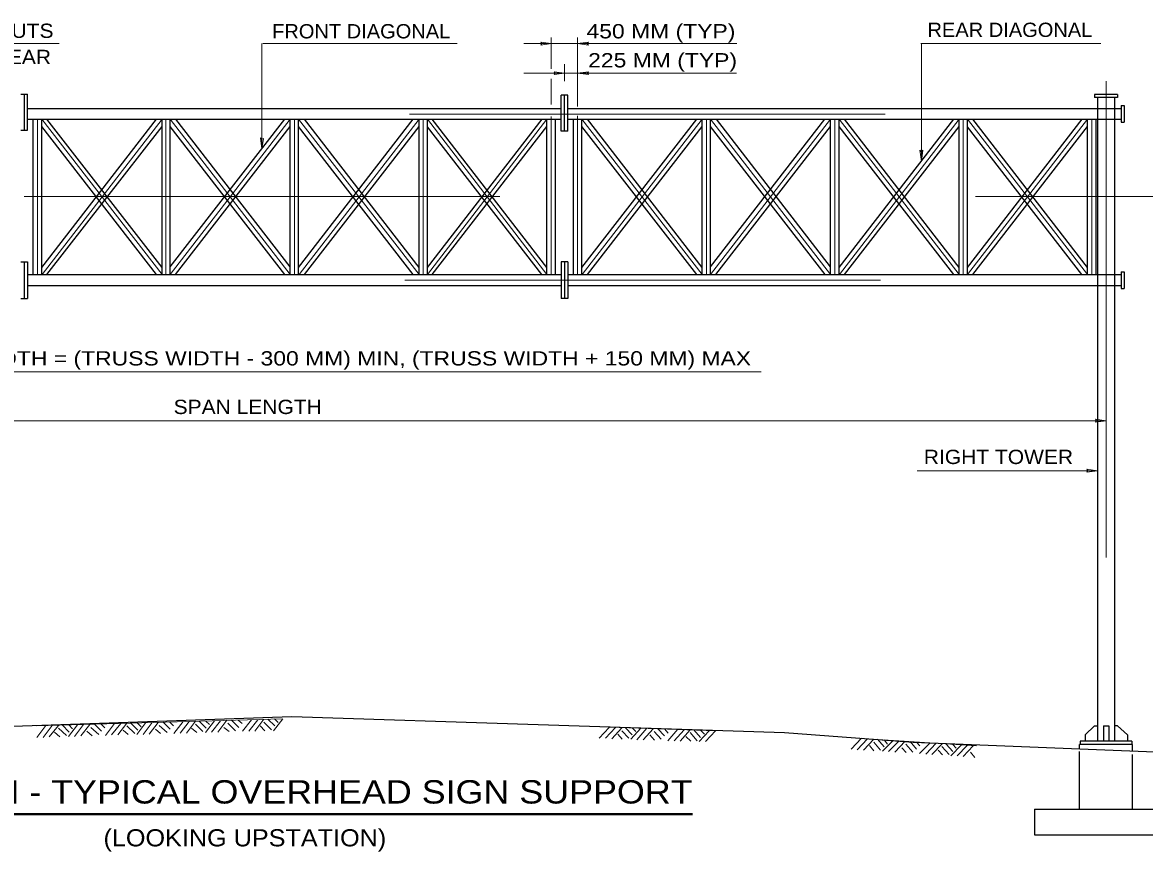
# Model space of a CAD drawing. Extents: x 312601.858 to 312602.699, y 144420.109 to 144420.704.
# Drawn here: x 312602.1757 to 312602.4116, y 144420.4027 to 144420.5768 of the extents above; entities that cross this region are included whole.
import ezdxf
from ezdxf.enums import TextEntityAlignment as Align

# ---------------------------------------------------------------- set-up
doc = ezdxf.new("R2010")
doc.units = 0
doc.header["$LTSCALE"] = 0.0012
doc.linetypes.add('DOT_DASHED', pattern=[7.7, 5, -1.2, 0.3, -1.2])
doc.linetypes.add('LONG_DASHED', pattern=[7.5, 6, -1.5])
doc.layers.add('1', color=7, linetype='Continuous', lineweight=25)
doc.layers.add('2', color=7, linetype='Continuous', lineweight=13)

msp = doc.modelspace()

# ---------------------------------------------------------------- linework, layer by layer
at = {"layer": '1', "lineweight": 13}
for p, q in [((312602.2869, 144420.5737), (312602.2869, 144420.5671)), ((312602.2924, 144420.5737), (312602.2924, 144420.5592)), ((312602.1392, 144420.5724), (312602.1835, 144420.5724)), ((312602.2263, 144420.5724), (312602.2671, 144420.5724)), ((312602.3646, 144420.5724), (312602.4024, 144420.5724)), ((312602.3647, 144420.5724), (312602.3647, 144420.5477)), ((312602.2897, 144420.5645), (312602.2897, 144420.5681)), ((312602.2869, 144420.565), (312602.2869, 144420.5596)), ((312602.4053, 144420.5127), (312602.4053, 144420.5139)), ((312602.0623, 144420.4932), (312602.4035, 144420.4932)), ((312602.3638, 144420.4827), (312602.4017, 144420.4827)), ((312602.4053, 144420.431), (312602.4053, 144420.4322))]:
    msp.add_line(p, q, dxfattribs=at)
at = {"layer": '1', "linetype": 'DOT_DASHED', "lineweight": 13}
for p, q in [((312602.4035, 144420.5645), (312602.4035, 144420.4281)), ((312602.0571, 144420.5576), (312602.4098, 144420.5576)), ((312602.1789, 144420.5239), (312602.1789, 144420.5565)), ((312602.2051, 144420.5239), (312602.1798, 144420.5565)), ((312602.1799, 144420.5239), (312602.2051, 144420.5565)), ((312602.2059, 144420.5239), (312602.2059, 144420.5565)), ((312602.232, 144420.5239), (312602.2068, 144420.5565)), ((312602.2068, 144420.5239), (312602.232, 144420.5565)), ((312602.2329, 144420.5239), (312602.2329, 144420.5565)), ((312602.2591, 144420.5239), (312602.2338, 144420.5565)), ((312602.2339, 144420.5239), (312602.2591, 144420.5565)), ((312602.26, 144420.5239), (312602.26, 144420.5565)), ((312602.2609, 144420.5565), (312602.286, 144420.5239)), ((312602.2609, 144420.5239), (312602.286, 144420.5565)), ((312602.2869, 144420.5571), (312602.2869, 144420.5239)), ((312602.2924, 144420.5572), (312602.2924, 144420.5239)), ((312602.3186, 144420.5239), (312602.2933, 144420.5565)), ((312602.2934, 144420.5239), (312602.3186, 144420.5565)), ((312602.3195, 144420.5239), (312602.3195, 144420.5565)), ((312602.3456, 144420.5239), (312602.3204, 144420.5565)), ((312602.3204, 144420.5239), (312602.3456, 144420.5565)), ((312602.3465, 144420.5239), (312602.3465, 144420.5565)), ((312602.3726, 144420.5239), (312602.3474, 144420.5565)), ((312602.3475, 144420.5239), (312602.3726, 144420.5565)), ((312602.3735, 144420.5239), (312602.3735, 144420.5565)), ((312602.3744, 144420.5565), (312602.3996, 144420.5239)), ((312602.3744, 144420.5239), (312602.3996, 144420.5565)), ((312602.4005, 144420.5565), (312602.4005, 144420.5239)), ((312602.1761, 144420.5403), (312602.4195, 144420.5403)), ((312602.0561, 144420.5227), (312602.4099, 144420.5227))]:
    msp.add_line(p, q, dxfattribs=at)
at = {"layer": '1'}
for p, q in [((312602.1754, 144420.5618), (312602.1768, 144420.5618)), ((312602.1761, 144420.5618), (312602.1761, 144420.5542)), ((312602.2904, 144420.5616), (312602.289, 144420.5616)), ((312602.2897, 144420.554), (312602.2897, 144420.5616)), ((312602.2904, 144420.554), (312602.2904, 144420.5616)), ((312602.4059, 144420.5617), (312602.4011, 144420.5617)), ((312602.4011, 144420.5617), (312602.4011, 144420.5611)), ((312602.4059, 144420.5617), (312602.4059, 144420.5611)), ((312602.4059, 144420.5611), (312602.4011, 144420.5611)), ((312602.4017, 144420.5611), (312602.4017, 144420.4259)), ((312602.4053, 144420.5611), (312602.4053, 144420.4259)), ((312602.4067, 144420.5594), (312602.4067, 144420.5559)), ((312602.4067, 144420.5594), (312602.4073, 144420.5594)), ((312602.4073, 144420.5594), (312602.4073, 144420.5559)), ((312602.1768, 144420.5565), (312602.289, 144420.5565)), ((312602.178, 144420.5239), (312602.178, 144420.5565)), ((312602.1798, 144420.5239), (312602.1798, 144420.5565)), ((312602.2051, 144420.5254), (312602.1809, 144420.5565)), ((312602.2051, 144420.5239), (312602.2051, 144420.5565)), ((312602.2068, 144420.5239), (312602.2068, 144420.5565)), ((312602.2068, 144420.5255), (312602.2309, 144420.5565)), ((312602.232, 144420.5239), (312602.232, 144420.5565)), ((312602.2338, 144420.5239), (312602.2338, 144420.5565)), ((312602.2591, 144420.5254), (312602.235, 144420.5565)), ((312602.2591, 144420.5239), (312602.2591, 144420.5565)), ((312602.2609, 144420.5239), (312602.2609, 144420.5565)), ((312602.2609, 144420.5254), (312602.285, 144420.5565)), ((312602.286, 144420.5239), (312602.286, 144420.5565)), ((312602.2878, 144420.5239), (312602.2878, 144420.5565)), ((312602.2904, 144420.5588), (312602.4017, 144420.5588)), ((312602.2904, 144420.5565), (312602.4017, 144420.5565)), ((312602.2916, 144420.5239), (312602.2916, 144420.5565)), ((312602.2933, 144420.5239), (312602.2933, 144420.5565)), ((312602.3186, 144420.5254), (312602.2945, 144420.5565)), ((312602.3186, 144420.5239), (312602.3186, 144420.5565)), ((312602.3204, 144420.5239), (312602.3204, 144420.5565)), ((312602.3204, 144420.5255), (312602.3444, 144420.5565)), ((312602.3456, 144420.5239), (312602.3456, 144420.5565)), ((312602.3474, 144420.5239), (312602.3474, 144420.5565)), ((312602.3726, 144420.5254), (312602.3485, 144420.5565)), ((312602.3726, 144420.5239), (312602.3726, 144420.5565)), ((312602.3744, 144420.5239), (312602.3744, 144420.5565)), ((312602.3744, 144420.5254), (312602.3985, 144420.5565)), ((312602.3996, 144420.5239), (312602.3996, 144420.5565)), ((312602.4014, 144420.5239), (312602.4014, 144420.5565)), ((312602.4053, 144420.5588), (312602.4067, 144420.5588)), ((312602.4053, 144420.5565), (312602.4067, 144420.5565)), ((312602.1754, 144420.5542), (312602.1768, 144420.5542)), ((312602.2039, 144420.5239), (312602.1798, 144420.555)), ((312602.2079, 144420.5239), (312602.232, 144420.555)), ((312602.2579, 144420.5239), (312602.2338, 144420.555)), ((312602.2619, 144420.5239), (312602.286, 144420.555)), ((312602.3175, 144420.5239), (312602.2933, 144420.555)), ((312602.3215, 144420.5239), (312602.3456, 144420.555)), ((312602.3715, 144420.5239), (312602.3474, 144420.555)), ((312602.3755, 144420.5239), (312602.3996, 144420.555)), ((312602.4067, 144420.5559), (312602.4073, 144420.5559)), ((312602.1761, 144420.5266), (312602.1761, 144420.5189)), ((312602.2897, 144420.5266), (312602.2897, 144420.5189)), ((312602.2904, 144420.5266), (312602.2904, 144420.5189)), ((312602.1768, 144420.5239), (312602.289, 144420.5239)), ((312602.2904, 144420.5239), (312602.4017, 144420.5239)), ((312602.4053, 144420.5239), (312602.4067, 144420.5239)), ((312602.4067, 144420.5245), (312602.4067, 144420.521)), ((312602.4067, 144420.5245), (312602.4073, 144420.5245)), ((312602.4073, 144420.5245), (312602.4073, 144420.521)), ((312602.1768, 144420.5216), (312602.289, 144420.5216)), ((312602.2904, 144420.5216), (312602.4017, 144420.5216)), ((312602.4053, 144420.5216), (312602.4067, 144420.5216)), ((312602.1754, 144420.5189), (312602.1768, 144420.5189)), ((312602.2904, 144420.5189), (312602.289, 144420.5189)), ((312602.4067, 144420.521), (312602.4073, 144420.521)), ((312602.403, 144420.4291), (312602.403, 144420.4259)), ((312602.403, 144420.4291), (312602.4041, 144420.4291)), ((312602.4041, 144420.4291), (312602.4041, 144420.4259)), ((312602.3991, 144420.4272), (312602.3991, 144420.4259)), ((312602.408, 144420.4272), (312602.408, 144420.4259)), ((312602.4091, 144420.4252), (312602.3979, 144420.4252)), ((312602.3979, 144420.4243), (312602.3979, 144420.4252)), ((312602.3981, 144420.4259), (312602.3981, 144420.4252)), ((312602.4089, 144420.4259), (312602.3981, 144420.4259)), ((312602.4089, 144420.4259), (312602.4089, 144420.4252)), ((312602.4091, 144420.4239), (312602.4091, 144420.4252))]:
    msp.add_line(p, q, dxfattribs=at)
at = {"layer": '1', "linetype": 'LONG_DASHED'}
for p, q in [((312602.1798, 144420.5254), (312602.2039, 144420.5565)), ((312602.232, 144420.5255), (312602.208, 144420.5565)), ((312602.2338, 144420.5254), (312602.2579, 144420.5565)), ((312602.286, 144420.5254), (312602.2619, 144420.5565)), ((312602.2933, 144420.5254), (312602.3175, 144420.5565)), ((312602.3456, 144420.5255), (312602.3216, 144420.5565)), ((312602.3474, 144420.5254), (312602.3715, 144420.5565)), ((312602.3996, 144420.5254), (312602.3755, 144420.5565)), ((312602.4017, 144420.5588), (312602.4053, 144420.5588)), ((312602.4017, 144420.5565), (312602.4053, 144420.5565)), ((312602.1809, 144420.5239), (312602.2051, 144420.555)), ((312602.2309, 144420.5239), (312602.2068, 144420.555)), ((312602.235, 144420.5239), (312602.2591, 144420.555)), ((312602.2849, 144420.5239), (312602.2609, 144420.5549)), ((312602.2945, 144420.5239), (312602.3186, 144420.555)), ((312602.3445, 144420.5239), (312602.3204, 144420.555)), ((312602.3485, 144420.5239), (312602.3726, 144420.555)), ((312602.3984, 144420.5239), (312602.3744, 144420.5549)), ((312602.4017, 144420.5239), (312602.4053, 144420.5239)), ((312602.4017, 144420.5216), (312602.4053, 144420.5216)), ((312602.3979, 144420.4116), (312602.3979, 144420.4237)), ((312602.4091, 144420.4116), (312602.4091, 144420.4231)), ((312602.3885, 144420.4116), (312602.4185, 144420.4116)), ((312602.3885, 144420.4062), (312602.4183, 144420.4062))]:
    msp.add_line(p, q, dxfattribs=at)
at = {"layer": '1', "lineweight": 13}
for points in [[(312602.2811, 144420.5724), (312602.2869, 144420.5724), (312602.2924, 144420.5724), (312602.3259, 144420.5724)], [(312602.2811, 144420.5662), (312602.2897, 144420.5662), (312602.2924, 144420.5662), (312602.3258, 144420.5662)], [(312602.1193, 144420.5035), (312602.1464, 144420.5035), (312602.331, 144420.5035)]]:
    msp.add_lwpolyline(points, dxfattribs=at)
for points in [[(312602.2847, 144420.5727), (312602.2869, 144420.5724), (312602.2847, 144420.5721), (312602.2849, 144420.5724)], [(312602.2947, 144420.5721), (312602.2924, 144420.5724), (312602.2947, 144420.5727), (312602.2944, 144420.5724)], [(312602.2875, 144420.5665), (312602.2897, 144420.5662), (312602.2875, 144420.5659), (312602.2877, 144420.5662)], [(312602.2947, 144420.5659), (312602.2924, 144420.5662), (312602.2947, 144420.5665), (312602.2944, 144420.5662)], [(312602.2264, 144420.5525), (312602.2261, 144420.5503), (312602.2258, 144420.5526), (312602.2261, 144420.5523)], [(312602.365, 144420.55), (312602.3647, 144420.5477), (312602.3644, 144420.55), (312602.3647, 144420.5497)], [(312602.4013, 144420.4935), (312602.4035, 144420.4932), (312602.4013, 144420.4929), (312602.4015, 144420.4932)], [(312602.3995, 144420.483), (312602.4017, 144420.4827), (312602.3995, 144420.4824), (312602.3997, 144420.4827)]]:
    msp.add_lwpolyline(points, close=True, dxfattribs=at)
at = {"layer": '1'}
for points in [[(312602.2904, 144420.554), (312602.289, 144420.554), (312602.289, 144420.5616)], [(312602.1754, 144420.5266), (312602.1768, 144420.5266), (312602.1768, 144420.5189)], [(312602.2904, 144420.5266), (312602.289, 144420.5266), (312602.289, 144420.5189)], [(312602.0446, 144420.4231), (312602.1024, 144420.4255), (312602.1292, 144420.4275), (312602.2324, 144420.4311), (312602.3359, 144420.4277), (312602.363, 144420.4257), (312602.4208, 144420.4234)], [(312602.3991, 144420.4272), (312602.4011, 144420.4291), (312602.4017, 144420.4291)], [(312602.408, 144420.4272), (312602.4059, 144420.4291), (312602.4053, 144420.4291)]]:
    msp.add_lwpolyline(points, dxfattribs=at)
for points in [[(312602.1768, 144420.5542), (312602.1768, 144420.5618)], [(312602.1768, 144420.5588), (312602.289, 144420.5588)]]:
    msp.add_open_spline(points, degree=1, dxfattribs=at)
at = {"layer": '2'}
for p, q in [((312602.2261, 144420.5724), (312602.2261, 144420.5504)), ((312602.1787, 144420.4291), (312602.2304, 144420.4306)), ((312602.1788, 144420.4267), (312602.1807, 144420.4292)), ((312602.1801, 144420.4267), (312602.182, 144420.4292)), ((312602.1814, 144420.4268), (312602.1833, 144420.4292)), ((312602.1841, 144420.4293), (312602.1856, 144420.4278)), ((312602.1854, 144420.4269), (312602.1873, 144420.4293)), ((312602.1855, 144420.4293), (312602.1863, 144420.4285)), ((312602.1867, 144420.4269), (312602.1886, 144420.4294)), ((312602.188, 144420.427), (312602.1899, 144420.4294)), ((312602.1909, 144420.4295), (312602.1924, 144420.428)), ((312602.1923, 144420.4295), (312602.1931, 144420.4287)), ((312602.1932, 144420.4271), (312602.1951, 144420.4296)), ((312602.1945, 144420.4272), (312602.1964, 144420.4296)), ((312602.1958, 144420.4272), (312602.1977, 144420.4297)), ((312602.1977, 144420.4291), (312602.1994, 144420.4275)), ((312602.1985, 144420.4297), (312602.2, 144420.4282)), ((312602.1998, 144420.4273), (312602.2017, 144420.4298)), ((312602.1999, 144420.4297), (312602.2007, 144420.4289)), ((312602.2011, 144420.4273), (312602.203, 144420.4298)), ((312602.2024, 144420.4274), (312602.2043, 144420.4298)), ((312602.2045, 144420.4292), (312602.2062, 144420.4277)), ((312602.2053, 144420.4299), (312602.2068, 144420.4284)), ((312602.2067, 144420.4299), (312602.2075, 144420.4291)), ((312602.2076, 144420.4275), (312602.2095, 144420.43)), ((312602.2089, 144420.4276), (312602.2108, 144420.43)), ((312602.2102, 144420.4276), (312602.2121, 144420.4301)), ((312602.2121, 144420.4295), (312602.2137, 144420.4279)), ((312602.2129, 144420.4301), (312602.2144, 144420.4286)), ((312602.2142, 144420.4277), (312602.2161, 144420.4302)), ((312602.2143, 144420.4301), (312602.2151, 144420.4294)), ((312602.2155, 144420.4278), (312602.2174, 144420.4302)), ((312602.2168, 144420.4278), (312602.2187, 144420.4303)), ((312602.2189, 144420.4297), (312602.2205, 144420.4281)), ((312602.2197, 144420.4303), (312602.2212, 144420.4288)), ((312602.2211, 144420.4303), (312602.2219, 144420.4296)), ((312602.222, 144420.428), (312602.2239, 144420.4304)), ((312602.2233, 144420.428), (312602.2252, 144420.4304)), ((312602.2246, 144420.428), (312602.2265, 144420.4305)), ((312602.2257, 144420.4291), (312602.2267, 144420.4281)), ((312602.2265, 144420.4299), (312602.2281, 144420.4283)), ((312602.2273, 144420.4305), (312602.2288, 144420.4291)), ((312602.2285, 144420.4281), (312602.2305, 144420.4306)), ((312602.2287, 144420.4306), (312602.2295, 144420.4298)), ((312602.1825, 144420.4278), (312602.1836, 144420.4268)), ((312602.1833, 144420.4286), (312602.185, 144420.4271)), ((312602.1893, 144420.428), (312602.1904, 144420.427)), ((312602.1901, 144420.4288), (312602.1918, 144420.4273)), ((312602.1969, 144420.4282), (312602.198, 144420.4273)), ((312602.2037, 144420.4284), (312602.2048, 144420.4275)), ((312602.2113, 144420.4286), (312602.2124, 144420.4277)), ((312602.2181, 144420.4288), (312602.2192, 144420.4279)), ((312602.297, 144420.4265), (312602.2991, 144420.4288)), ((312602.2971, 144420.4289), (312602.3215, 144420.4281)), ((312602.2983, 144420.4265), (312602.3004, 144420.4288)), ((312602.2996, 144420.4264), (312602.3017, 144420.4287)), ((312602.3009, 144420.4274), (312602.3018, 144420.4263)), ((312602.3017, 144420.4281), (312602.3032, 144420.4265)), ((312602.3025, 144420.4287), (312602.3039, 144420.4272)), ((312602.3036, 144420.4263), (312602.3057, 144420.4286)), ((312602.3039, 144420.4287), (312602.3047, 144420.4279)), ((312602.3049, 144420.4262), (312602.307, 144420.4286)), ((312602.3062, 144420.4262), (312602.3083, 144420.4285)), ((312602.3076, 144420.4272), (312602.3086, 144420.4261)), ((312602.3085, 144420.4279), (312602.31, 144420.4263)), ((312602.3093, 144420.4285), (312602.3107, 144420.427)), ((312602.3107, 144420.4285), (312602.3115, 144420.4276)), ((312602.3114, 144420.426), (312602.3135, 144420.4284)), ((312602.3127, 144420.426), (312602.3148, 144420.4283)), ((312602.314, 144420.4259), (312602.3161, 144420.4283)), ((312602.3152, 144420.4269), (312602.3162, 144420.4259)), ((312602.3161, 144420.4277), (312602.3176, 144420.426)), ((312602.3169, 144420.4283), (312602.3183, 144420.4267)), ((312602.318, 144420.4258), (312602.3201, 144420.4281)), ((312602.3183, 144420.4282), (312602.3191, 144420.4274)), ((312602.3193, 144420.4258), (312602.3214, 144420.4281)), ((312602.3499, 144420.4242), (312602.3521, 144420.4265)), ((312602.3501, 144420.4266), (312602.3763, 144420.4249)), ((312602.3512, 144420.4241), (312602.3534, 144420.4264)), ((312602.3525, 144420.424), (312602.3547, 144420.4263)), ((312602.3538, 144420.425), (312602.3547, 144420.4239)), ((312602.3547, 144420.4257), (312602.3561, 144420.424)), ((312602.3555, 144420.4263), (312602.3569, 144420.4247)), ((312602.3565, 144420.4238), (312602.3587, 144420.426)), ((312602.3569, 144420.4262), (312602.3576, 144420.4253)), ((312602.3578, 144420.4237), (312602.36, 144420.426)), ((312602.3591, 144420.4236), (312602.3613, 144420.4259)), ((312602.3606, 144420.4245), (312602.3615, 144420.4235)), ((312602.3614, 144420.4253), (312602.3629, 144420.4236)), ((312602.3623, 144420.4258), (312602.3637, 144420.4242)), ((312602.3637, 144420.4257), (312602.3644, 144420.4249)), ((312602.3643, 144420.4233), (312602.3665, 144420.4255)), ((312602.3656, 144420.4232), (312602.3678, 144420.4255)), ((312602.3669, 144420.4231), (312602.3691, 144420.4254)), ((312602.369, 144420.4248), (312602.3705, 144420.4231)), ((312602.3699, 144420.4253), (312602.3713, 144420.4237)), ((312602.3709, 144420.4228), (312602.3731, 144420.4251)), ((312602.3713, 144420.4252), (312602.372, 144420.4244)), ((312602.3722, 144420.4228), (312602.3743, 144420.425)), ((312602.3735, 144420.4227), (312602.3756, 144420.4249)), ((312602.3682, 144420.424), (312602.3691, 144420.423)), ((312602.375, 144420.4236), (312602.3759, 144420.4225))]:
    msp.add_line(p, q, dxfattribs=at)
at = {"layer": '2', "lineweight": 40}
msp.add_line((312602.1329, 144420.4106), (312602.3166, 144420.4106), dxfattribs=at)
at = {"layer": '2', "linetype": 'LONG_DASHED', "lineweight": 25}
msp.add_line((312602.3885, 144420.4116), (312602.3885, 144420.4062), dxfattribs=at)

# ---------------------------------------------------------------- texts
at = {"layer": '2'}
for s, height, width, p in [('VERTICAL STRUTS', 0.003, 1.1, (312602.16205, 144420.5736)), ('FRONT DIAGONAL', 0.003, 1.05, (312602.24695, 144420.5735)), ('450 MM (TYP)', 0.003, 1.2, (312602.30995, 144420.5735)), ('REAR DIAGONAL', 0.003, 1.05, (312602.3833, 144420.5738)), ('FRONT AND REAR', 0.003, 1.1, (312602.16215, 144420.5681)), ('225 MM (TYP)', 0.003, 1.2, (312602.3103, 144420.5674)), ('PANEL WIDTH = (TRUSS WIDTH - 300 MM) MIN, (TRUSS WIDTH + 150 MM) MAX', 0.003, 1.2, (312602.2385, 144420.5048)), ('ELEVATION - TYPICAL OVERHEAD SIGN SUPPORT', 0.0049, 1.15, (312602.2247, 144420.4128)), ('(LOOKING UPSTATION)', 0.0036, 1.1, (312602.2225, 144420.4038))]:
    msp.add_text(s, height=height, dxfattribs=dict(at, width=width)).set_placement(p, align=Align.CENTER)
at = {"layer": '2', "width": 1.1}
for s, p in [(' SPAN LENGTH', (312602.2063, 144420.4946)), ('RIGHT TOWER', (312602.3652, 144420.4841))]:
    msp.add_text(s, height=0.003, dxfattribs=at).set_placement(p)

doc.saveas('drawing.dxf')
